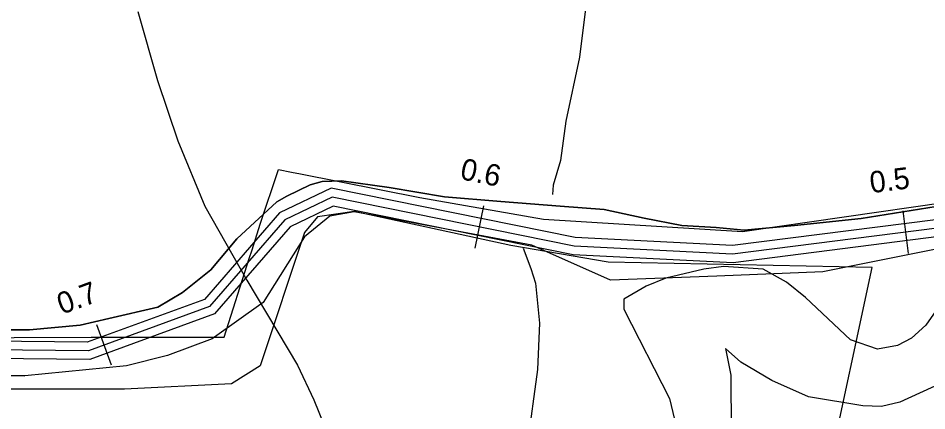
# Model space of a CAD drawing. Extents: x -662620 to -656370, y -1067090 to -1062990.
# Drawn here: x -659222 to -659010.6, y -1066477.7 to -1066386.4 of the extents above; entities that cross this region are included whole.
import ezdxf

# ---------------------------------------------------------------- set-up
doc = ezdxf.new("R2010")
doc.units = 0
for name, color, linetype in [('Default', 7, 'Continuous'), ('HRANICE_KATASTRÁLNÍHO_ÚZEMÍ', 7, 'Continuous'), ('OBVOD_PÚ', 7, 'Continuous'), ('Ochr__pás__vod__zdroje_II__stupně', 7, 'Continuous'), ('ORNÁ_PŮDA_-_STÁVAJÍCÍ', 7, 'Continuous'), ('OSTATNÍ_PLOCHA_-_STÁVAJÍCÍ', 7, 'Continuous'), ('POLNÍ_CESTA_STÁVAJÍCÍ_-_KRAJ', 7, 'Continuous'), ('POLNÍ_CESTA_STÁVAJÍCÍ_-_OSA', 7, 'Continuous'), ('VRSTEVNICE_ZDŮRAZNĚNÁ', 7, 'Continuous'), ('VRSTEVNICE_ZÁKLADNÍ', 7, 'Continuous')]:
    doc.layers.add(name, color=color, linetype=linetype)

msp = doc.modelspace()

# ---------------------------------------------------------------- linework, layer by layer
at = {"layer": 'HRANICE_KATASTRÁLNÍHO_ÚZEMÍ'}
msp.add_lwpolyline([(-659310.15, -1066382.24), (-659317.01, -1066430.63), (-659318.41, -1066431.28), (-659318.91, -1066433.96), (-659319.99, -1066439.62), (-659317.55, -1066444.53), (-659310.45, -1066460.83), (-659309.21, -1066460.87), (-659294.61, -1066460.93), (-659205.02, -1066460.53), (-659174.15, -1066460.53), (-659168.3, -1066442.25), (-659167.63, -1066440.26), (-659165.75, -1066434.24), (-659161.5, -1066421.58), (-659158.45, -1066422.18), (-659156.37, -1066422.59), (-659128.61, -1066428.1), (-659099.81, -1066433.11), (-659053.57, -1066436), (-659006.19, -1066429.15)], dxfattribs=at)
at = {"layer": 'OBVOD_PÚ'}
for points in [[(-659149.5, -1066432.39), (-659155.4, -1066437.2)], [(-659143.89, -1066431.36), (-659149.5, -1066432.39)], [(-659102.54, -1066439.13), (-659143.89, -1066431.36)], [(-658978.73, -1066434.12), (-659034.87, -1066445.35)], [(-659155.4, -1066437.2), (-659165.05, -1066452.46)], [(-659084.25, -1066447.25), (-659102.54, -1066439.13)], [(-659034.87, -1066445.35), (-659059.53, -1066446.36)], [(-659059.53, -1066446.36), (-659084.25, -1066447.25)], [(-659165.05, -1066452.46), (-659176.87, -1066460.91)], [(-659176.87, -1066460.91), (-659187.3, -1066464.78)], [(-659187.3, -1066464.78), (-659196.81, -1066467.19)], [(-659196.81, -1066467.19), (-659220.49, -1066469.56)], [(-659246.58, -1066468.94), (-659220.49, -1066469.56)]]:
    msp.add_lwpolyline(points, dxfattribs=at)
at = {"layer": 'Ochr__pás__vod__zdroje_II__stupně'}
msp.add_lwpolyline([(-659079.54, -1066704.27), (-659055.18, -1066589.41), (-659038.55, -1066512.51), (-659026.99, -1066508.85), (-659033.68, -1066492.42), (-659023.34, -1066444.34), (-659084.81, -1066443.12), (-659107.4, -1066439.22), (-659143.86, -1066431.32), (-659152.37, -1066432.53), (-659155.4, -1066436.18), (-659165.73, -1066467.17), (-659172.41, -1066471.42), (-659197.33, -1066472.64), (-659273.26, -1066472.64), (-659307.3, -1066472.64), (-659314.18, -1066474.53), (-659319.05, -1066473.39), (-659311.11, -1066439.28), (-659557.2, -1066499.13)], dxfattribs=at)
at = {"layer": 'ORNÁ_PŮDA_-_STÁVAJÍCÍ'}
for p, q in [((-659151.33, -1066424.36), (-659154.12, -1066425.12)), ((-659146.82, -1066424.22), (-659151.33, -1066424.36)), ((-659135.72, -1066425.76), (-659146.82, -1066424.22)), ((-659154.12, -1066425.12), (-659159.57, -1066427.76)), ((-659122.85, -1066427.92), (-659135.72, -1066425.76)), ((-659161.87, -1066429.1), (-659171.19, -1066437.64)), ((-659159.57, -1066427.76), (-659161.87, -1066429.1)), ((-659109.73, -1066429.01), (-659122.85, -1066427.92)), ((-659095.92, -1066430.08), (-659109.73, -1066429.01)), ((-659085.7, -1066430.87), (-659095.92, -1066430.08)), ((-659076.37, -1066432.9), (-659085.7, -1066430.87)), ((-659006.52, -1066429.83), (-659025.95, -1066432.95)), ((-659067.66, -1066434.55), (-659076.37, -1066432.9)), ((-659025.95, -1066432.95), (-659041.42, -1066434.61)), ((-659059.63, -1066435.04), (-659067.66, -1066434.55)), ((-659053.11, -1066435.67), (-659059.63, -1066435.04)), ((-659041.42, -1066434.61), (-659053.11, -1066435.67)), ((-659171.19, -1066437.64), (-659177.25, -1066444.88)), ((-659177.25, -1066444.88), (-659183.79, -1066450.16)), ((-659183.79, -1066450.16), (-659189.54, -1066453.56)), ((-659189.54, -1066453.56), (-659200.92, -1066456.23)), ((-659200.92, -1066456.23), (-659207.63, -1066457.71)), ((-659207.63, -1066457.71), (-659219.38, -1066458.8)), ((-659219.38, -1066458.8), (-659233.1, -1066458.84))]:
    msp.add_line(p, q, dxfattribs=at)
msp.add_lwpolyline([(-659006.52, -1066429.83), (-659025.95, -1066432.95), (-659041.42, -1066434.61), (-659053.11, -1066435.67), (-659059.63, -1066435.04), (-659067.66, -1066434.55), (-659076.37, -1066432.9), (-659085.7, -1066430.87), (-659095.92, -1066430.08), (-659109.73, -1066429.01), (-659122.85, -1066427.92), (-659135.72, -1066425.76), (-659146.82, -1066424.22), (-659151.33, -1066424.36), (-659154.12, -1066425.12), (-659159.57, -1066427.76), (-659161.87, -1066429.1), (-659171.19, -1066437.64), (-659177.25, -1066444.88), (-659183.79, -1066450.16), (-659189.54, -1066453.56), (-659200.92, -1066456.23), (-659207.63, -1066457.71), (-659219.38, -1066458.8), (-659233.1, -1066458.84)], dxfattribs=at)
at = {"layer": 'OSTATNÍ_PLOCHA_-_STÁVAJÍCÍ'}
for p, q in [((-659154.12, -1066425.12), (-659151.33, -1066424.36)), ((-659154.12, -1066425.12), (-659151.33, -1066424.36)), ((-659151.33, -1066424.36), (-659146.82, -1066424.22)), ((-659151.33, -1066424.36), (-659146.82, -1066424.22)), ((-659146.82, -1066424.22), (-659135.72, -1066425.76)), ((-659146.82, -1066424.22), (-659135.72, -1066425.76)), ((-659159.57, -1066427.76), (-659154.12, -1066425.12)), ((-659159.57, -1066427.76), (-659154.12, -1066425.12)), ((-659135.72, -1066425.76), (-659122.85, -1066427.92)), ((-659135.72, -1066425.76), (-659122.85, -1066427.92)), ((-659171.19, -1066437.64), (-659161.87, -1066429.1)), ((-659171.19, -1066437.64), (-659161.87, -1066429.1)), ((-659161.87, -1066429.1), (-659159.57, -1066427.76)), ((-659161.87, -1066429.1), (-659159.57, -1066427.76)), ((-659122.85, -1066427.92), (-659109.73, -1066429.01)), ((-659122.85, -1066427.92), (-659109.73, -1066429.01)), ((-659109.73, -1066429.01), (-659095.92, -1066430.08)), ((-659109.73, -1066429.01), (-659095.92, -1066430.08)), ((-659095.92, -1066430.08), (-659085.7, -1066430.87)), ((-659095.92, -1066430.08), (-659085.7, -1066430.87)), ((-659085.7, -1066430.87), (-659076.37, -1066432.9)), ((-659085.7, -1066430.87), (-659076.37, -1066432.9)), ((-659025.95, -1066432.95), (-659006.52, -1066429.83)), ((-659025.95, -1066432.95), (-659006.52, -1066429.83)), ((-659149.5, -1066432.39), (-659155.4, -1066437.2)), ((-659149.5, -1066432.39), (-659155.4, -1066437.2)), ((-659143.89, -1066431.36), (-659149.5, -1066432.39)), ((-659143.89, -1066431.36), (-659149.5, -1066432.39)), ((-659102.54, -1066439.13), (-659143.89, -1066431.36)), ((-659102.54, -1066439.13), (-659143.89, -1066431.36)), ((-659076.37, -1066432.9), (-659067.66, -1066434.55)), ((-659076.37, -1066432.9), (-659067.66, -1066434.55)), ((-659041.42, -1066434.61), (-659025.95, -1066432.95)), ((-659041.42, -1066434.61), (-659025.95, -1066432.95)), ((-659067.66, -1066434.55), (-659059.63, -1066435.04)), ((-659067.66, -1066434.55), (-659059.63, -1066435.04)), ((-659059.63, -1066435.04), (-659053.11, -1066435.67)), ((-659059.63, -1066435.04), (-659053.11, -1066435.67)), ((-659053.11, -1066435.67), (-659041.42, -1066434.61)), ((-659053.11, -1066435.67), (-659041.42, -1066434.61)), ((-658978.73, -1066434.12), (-659034.87, -1066445.35)), ((-658978.73, -1066434.12), (-659034.87, -1066445.35)), ((-659155.4, -1066437.2), (-659165.05, -1066452.46)), ((-659155.4, -1066437.2), (-659165.05, -1066452.46)), ((-659177.25, -1066444.88), (-659171.19, -1066437.64)), ((-659177.25, -1066444.88), (-659171.19, -1066437.64)), ((-659084.25, -1066447.25), (-659102.54, -1066439.13)), ((-659084.25, -1066447.25), (-659102.54, -1066439.13)), ((-659183.79, -1066450.16), (-659177.25, -1066444.88)), ((-659183.79, -1066450.16), (-659177.25, -1066444.88)), ((-659034.87, -1066445.35), (-659059.53, -1066446.36)), ((-659034.87, -1066445.35), (-659059.53, -1066446.36)), ((-659059.53, -1066446.36), (-659084.25, -1066447.25)), ((-659059.53, -1066446.36), (-659084.25, -1066447.25)), ((-659189.54, -1066453.56), (-659183.79, -1066450.16)), ((-659189.54, -1066453.56), (-659183.79, -1066450.16)), ((-659200.92, -1066456.23), (-659189.54, -1066453.56)), ((-659200.92, -1066456.23), (-659189.54, -1066453.56)), ((-659165.05, -1066452.46), (-659176.87, -1066460.91)), ((-659165.05, -1066452.46), (-659176.87, -1066460.91)), ((-659207.63, -1066457.71), (-659200.92, -1066456.23)), ((-659207.63, -1066457.71), (-659200.92, -1066456.23)), ((-659219.38, -1066458.8), (-659207.63, -1066457.71)), ((-659219.38, -1066458.8), (-659207.63, -1066457.71)), ((-659233.1, -1066458.84), (-659219.38, -1066458.8)), ((-659233.1, -1066458.84), (-659219.38, -1066458.8)), ((-659176.87, -1066460.91), (-659187.3, -1066464.78)), ((-659176.87, -1066460.91), (-659187.3, -1066464.78)), ((-659187.3, -1066464.78), (-659196.81, -1066467.19)), ((-659187.3, -1066464.78), (-659196.81, -1066467.19)), ((-659196.81, -1066467.19), (-659220.49, -1066469.56)), ((-659196.81, -1066467.19), (-659220.49, -1066469.56)), ((-659220.49, -1066469.56), (-659246.58, -1066468.94)), ((-659220.49, -1066469.56), (-659246.58, -1066468.94))]:
    msp.add_line(p, q, dxfattribs=at)
for points in [[(-659233.1, -1066458.84), (-659219.38, -1066458.8), (-659207.63, -1066457.71), (-659200.92, -1066456.23), (-659189.54, -1066453.56), (-659183.79, -1066450.16), (-659177.25, -1066444.88), (-659171.19, -1066437.64), (-659161.87, -1066429.1), (-659159.57, -1066427.76), (-659154.12, -1066425.12), (-659151.33, -1066424.36), (-659146.82, -1066424.22), (-659135.72, -1066425.76), (-659122.85, -1066427.92), (-659109.73, -1066429.01), (-659095.92, -1066430.08), (-659085.7, -1066430.87), (-659076.37, -1066432.9), (-659067.66, -1066434.55), (-659059.63, -1066435.04), (-659053.11, -1066435.67), (-659041.42, -1066434.61), (-659025.95, -1066432.95), (-659006.52, -1066429.83)], [(-659233.1, -1066458.84), (-659219.38, -1066458.8), (-659207.63, -1066457.71), (-659200.92, -1066456.23), (-659189.54, -1066453.56), (-659183.79, -1066450.16), (-659177.25, -1066444.88), (-659171.19, -1066437.64), (-659161.87, -1066429.1), (-659159.57, -1066427.76), (-659154.12, -1066425.12), (-659151.33, -1066424.36), (-659146.82, -1066424.22), (-659135.72, -1066425.76), (-659122.85, -1066427.92), (-659109.73, -1066429.01), (-659095.92, -1066430.08), (-659085.7, -1066430.87), (-659076.37, -1066432.9), (-659067.66, -1066434.55), (-659059.63, -1066435.04), (-659053.11, -1066435.67), (-659041.42, -1066434.61), (-659025.95, -1066432.95), (-659006.52, -1066429.83)], [(-658978.73, -1066434.12), (-659034.87, -1066445.35), (-659059.53, -1066446.36), (-659084.25, -1066447.25), (-659102.54, -1066439.13), (-659143.89, -1066431.36), (-659149.5, -1066432.39), (-659155.4, -1066437.2), (-659165.05, -1066452.46), (-659176.87, -1066460.91), (-659187.3, -1066464.78), (-659196.81, -1066467.19), (-659220.49, -1066469.56), (-659246.58, -1066468.94)], [(-658978.73, -1066434.12), (-659034.87, -1066445.35), (-659059.53, -1066446.36), (-659084.25, -1066447.25), (-659102.54, -1066439.13), (-659143.89, -1066431.36), (-659149.5, -1066432.39), (-659155.4, -1066437.2), (-659165.05, -1066452.46), (-659176.87, -1066460.91), (-659187.3, -1066464.78), (-659196.81, -1066467.19), (-659220.49, -1066469.56), (-659246.58, -1066468.94)]]:
    msp.add_lwpolyline(points, dxfattribs=at)
at = {"layer": 'POLNÍ_CESTA_STÁVAJÍCÍ_-_KRAJ'}
for points in [[(-658524.77, -1066416.91), (-658585.14, -1066399.5), (-658627.95, -1066387.63), (-658692.63, -1066382.35), (-658745.41, -1066382.35), (-658844.82, -1066394.86), (-658910.58, -1066405.85), (-659008.67, -1066433.22), (-659055.89, -1066439.26), (-659092.46, -1066437.38), (-659149.26, -1066425.87), (-659161.27, -1066431.66), (-659178.7, -1066451.74), (-659206.01, -1066461.71), (-659282.28, -1066460.95), (-659319.31, -1066453.29)], [(-658525.87, -1066420.75), (-658586.23, -1066403.35), (-658628.66, -1066391.58), (-658692.79, -1066386.35), (-658745.16, -1066386.35), (-658844.24, -1066398.82), (-658909.71, -1066409.76), (-659007.88, -1066437.15), (-659055.74, -1066443.28), (-659092.96, -1066441.36), (-659148.74, -1066430.05), (-659158.79, -1066434.91), (-659176.35, -1066455.14), (-659205.33, -1066465.71), (-659282.71, -1066464.95), (-659320.12, -1066457.21)]]:
    msp.add_lwpolyline(points, dxfattribs=at)
at = {"layer": 'POLNÍ_CESTA_STÁVAJÍCÍ_-_OSA'}
for points in [[(-658525.32, -1066418.83), (-658585.69, -1066401.42), (-658628.3, -1066389.61), (-658692.71, -1066384.35), (-658745.29, -1066384.35), (-658844.53, -1066396.84), (-658910.15, -1066407.8), (-659008.28, -1066435.19), (-659055.82, -1066441.27), (-659092.71, -1066439.37), (-659149, -1066427.96), (-659160.03, -1066433.28), (-659177.52, -1066453.44), (-659205.67, -1066463.71), (-659282.5, -1066462.95), (-659319.71, -1066455.25)], [(-659115.71, -1066439.81), (-659113.72, -1066430.01)], [(-659014.9, -1066441.08), (-659016.17, -1066431.16)], [(-659200.31, -1066467.08), (-659203.74, -1066457.68)]]:
    msp.add_lwpolyline(points, dxfattribs=at)
at = {"layer": 'VRSTEVNICE_ZDŮRAZNĚNÁ'}
msp.add_lwpolyline([(-659005.01, -1066449.31), (-659010.91, -1066457.74), (-659014.2, -1066460.75), (-659017.5, -1066462.47), (-659022.09, -1066463.33), (-659028.39, -1066461.18), (-659038.85, -1066451.29), (-659043.3, -1066447.71), (-659048.74, -1066444.7), (-659057.92, -1066444.13), (-659062.5, -1066444.7), (-659071.39, -1066446.85), (-659075.97, -1066448.71), (-659081.13, -1066451.72), (-659081.13, -1066454.02), (-659070.53, -1066474.8), (-659069.38, -1066479.67)], dxfattribs=at)
at = {"layer": 'VRSTEVNICE_ZÁKLADNÍ'}
for points in [[(-659156.8, -1066260.97), (-659146.77, -1066265.84), (-659134.16, -1066274.15), (-659123.84, -1066283.33), (-659115.77, -1066292.78), (-659110.51, -1066300.67), (-659102.34, -1066316.29), (-659094.6, -1066334.63), (-659089.3, -1066355.27), (-659088.44, -1066364.44), (-659088.44, -1066372.47), (-659089.59, -1066383.94), (-659090.02, -1066384.22), (-659091.45, -1066395.4), (-659094.6, -1066410.31), (-659095.89, -1066419.48), (-659097.61, -1066425.21), (-659097.76, -1066427.36)], [(-659156.8, -1066260.97), (-659146.77, -1066265.84), (-659134.16, -1066274.15), (-659123.84, -1066283.33), (-659115.77, -1066292.78), (-659110.51, -1066300.67), (-659102.34, -1066316.29), (-659094.6, -1066334.63), (-659089.3, -1066355.27), (-659088.44, -1066364.44), (-659088.44, -1066372.47), (-659089.59, -1066383.94), (-659090.02, -1066384.22), (-659091.45, -1066395.4), (-659094.6, -1066410.31), (-659095.89, -1066419.48), (-659097.61, -1066425.21), (-659097.76, -1066427.36)], [(-659194.21, -1066384.8), (-659189.62, -1066400.85), (-659184.89, -1066414.89), (-659178.59, -1066430.08), (-659168.84, -1066447.28), (-659157.09, -1066467.06), (-659153.22, -1066475.09), (-659148.63, -1066486.55), (-659146.63, -1066494.29), (-659145.46, -1066505.79), (-659145.88, -1066513.8), (-659147.63, -1066523.53), (-659148.92, -1066526.68), (-659152.5, -1066533.56), (-659159.24, -1066542.73), (-659166.41, -1066550.04), (-659170.56, -1066554.48), (-659184.61, -1066573.4), (-659189.62, -1066581.14), (-659193.49, -1066589.17), (-659195.5, -1066594.9), (-659197.65, -1066604.07), (-659200.29, -1066621.83), (-659202.95, -1066634.88)], [(-659194.21, -1066384.8), (-659189.62, -1066400.85), (-659184.89, -1066414.89), (-659178.59, -1066430.08), (-659168.84, -1066447.28), (-659157.09, -1066467.06), (-659153.22, -1066475.09), (-659148.63, -1066486.55), (-659146.63, -1066494.29), (-659145.46, -1066505.79), (-659145.88, -1066513.8), (-659147.63, -1066523.53), (-659148.92, -1066526.68), (-659152.5, -1066533.56), (-659159.24, -1066542.73), (-659166.41, -1066550.04), (-659170.56, -1066554.48), (-659184.61, -1066573.4), (-659189.62, -1066581.14), (-659193.49, -1066589.17), (-659195.5, -1066594.9), (-659197.65, -1066604.07), (-659200.29, -1066621.83), (-659202.95, -1066634.88)], [(-659104.52, -1066439.86), (-659102.77, -1066444.56), (-659101.69, -1066447.99), (-659100.77, -1066457.31), (-659101.2, -1066468.06), (-659103.63, -1066485.69), (-659105.93, -1066496.01), (-659108.14, -1066502.82), (-659110.51, -1066507.76), (-659112.38, -1066512.2), (-659119.11, -1066524.1), (-659128.86, -1066536.57), (-659138.46, -1066546.17), (-659151.07, -1066556.92), (-659157.66, -1066563.22), (-659177.3, -1066585.58), (-659184.03, -1066594.32), (-659187.33, -1066599.63), (-659190.2, -1066606.51), (-659190.63, -1066606.65), (-659193.06, -1066614.68), (-659200.23, -1066651.94)], [(-659104.52, -1066439.86), (-659102.77, -1066444.56), (-659101.69, -1066447.99), (-659100.77, -1066457.31), (-659101.2, -1066468.06), (-659103.63, -1066485.69), (-659105.93, -1066496.01), (-659108.14, -1066502.82), (-659110.51, -1066507.76), (-659112.38, -1066512.2), (-659119.11, -1066524.1), (-659128.86, -1066536.57), (-659138.46, -1066546.17), (-659151.07, -1066556.92), (-659157.66, -1066563.22), (-659177.3, -1066585.58), (-659184.03, -1066594.32), (-659187.33, -1066599.63), (-659190.2, -1066606.51), (-659190.63, -1066606.65), (-659193.06, -1066614.68), (-659200.23, -1066651.94)], [(-659006.89, -1066471.07), (-659016.93, -1066475.66), (-659021.23, -1066476.66), (-659025.53, -1066476.52), (-659038.14, -1066474.37), (-659046.74, -1066470.64), (-659053.9, -1066466.34), (-659057.51, -1066463.2), (-659056.21, -1066469.35), (-659056.15, -1066482.5)], [(-659006.89, -1066471.07), (-659016.93, -1066475.66), (-659021.23, -1066476.66), (-659025.53, -1066476.52), (-659038.14, -1066474.37), (-659046.74, -1066470.64), (-659053.9, -1066466.34), (-659057.51, -1066463.2), (-659056.21, -1066469.35), (-659056.15, -1066482.5)]]:
    msp.add_lwpolyline(points, dxfattribs=at)

# ---------------------------------------------------------------- texts
at = {"layer": 'Default'}
for s, rotation, p in [('0.6', 348.5412, (-659119.43, -1066423.75)), ('0.5', 7.2942, (-659023.61, -1066427.07)), ('0.7', 20.0452, (-659211.88, -1066455.33))]:
    msp.add_text(s, height=5, rotation=rotation, dxfattribs=at).set_placement(p)

doc.saveas('drawing.dxf')
